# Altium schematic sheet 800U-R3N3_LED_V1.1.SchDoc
size Letter
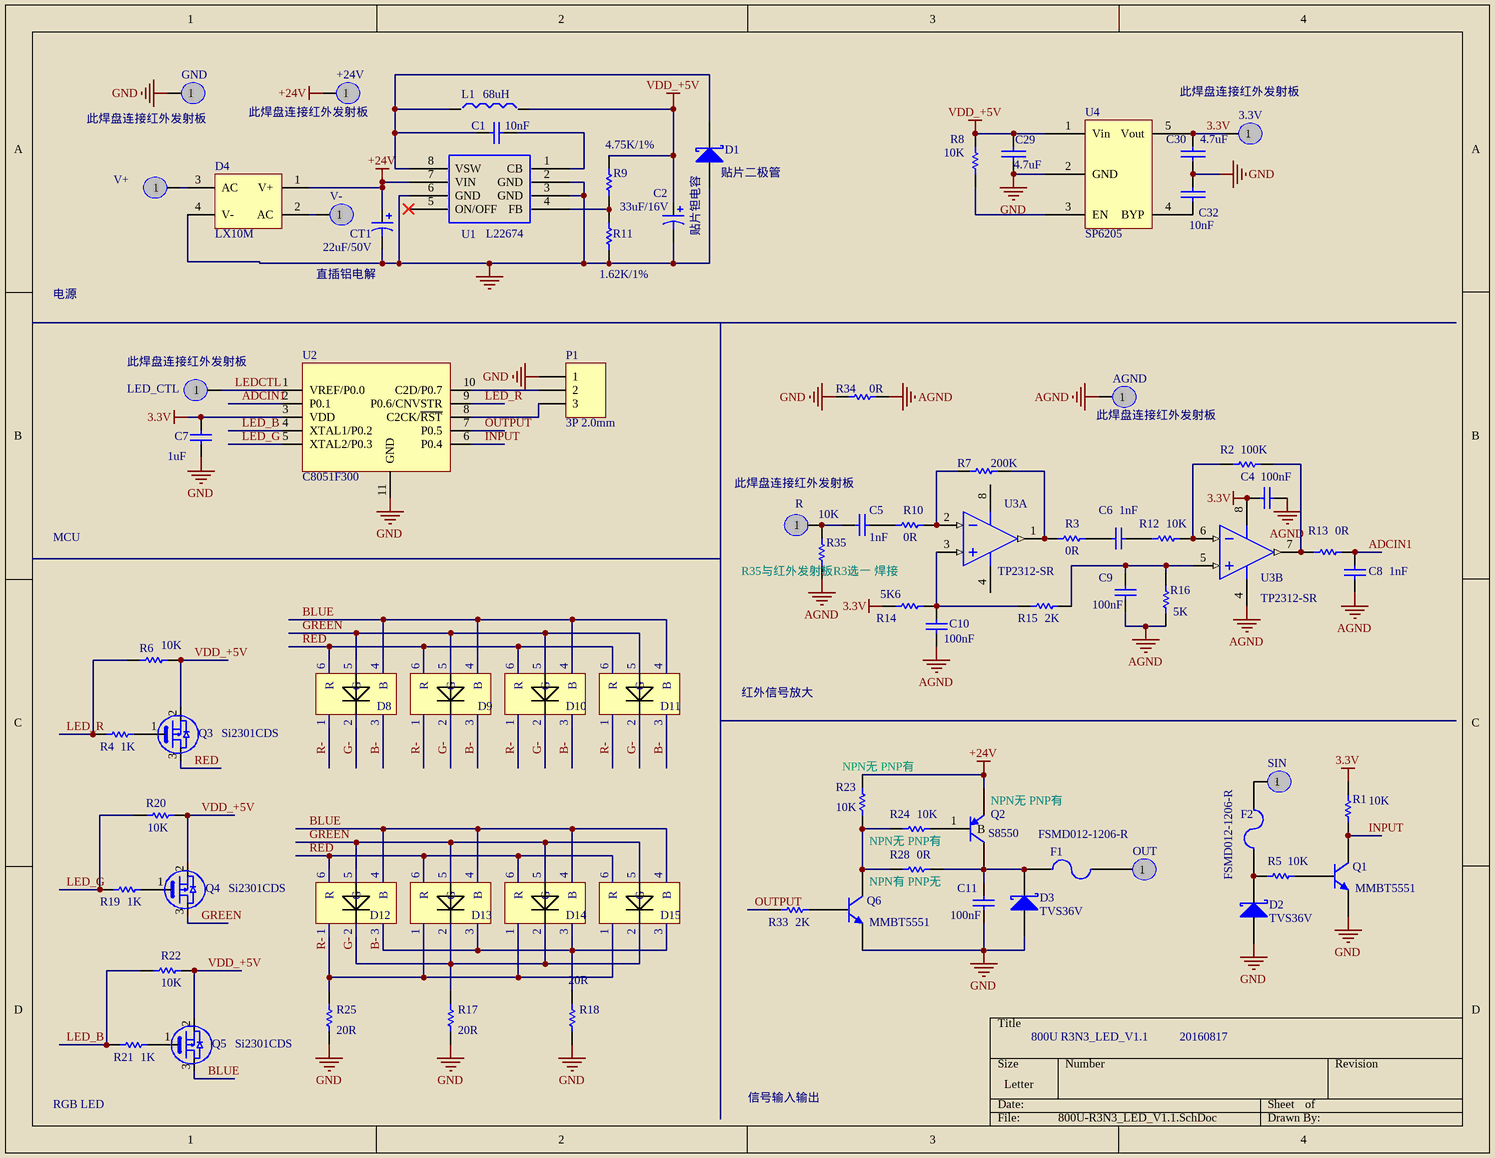
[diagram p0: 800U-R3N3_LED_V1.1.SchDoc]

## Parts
3.3V  (no value)  [HOLE_SMD]
+24V  (no value)  [HOLE_SMD]
AGND  (no value)  [HOLE_SMD]
C1  10nF  [C0603]
C2  33uF/16V  Kind: 贴片钽电容  [CT3528]
C4  100nF  [C0603]
C5  1nF  [C0603]
C6  1nF  [C0603]
C7  1uF  [C0603]
C8  1nF  [C0603]
C9  100nF  [C0603]
C10  100nF  [C0603]
C11  100nF  [C0603]
C29  4.7uF  [C0603]
C30  4.7uF  [C0603]
C32  10nF  [C0603]
CT1  22uF/50V  Kind: 直插铝电解  [RB0.1]
D1  Kind: 贴片二极管  [SMB]  (hidden comment: SS14)
D2  TVS36V  [HSMA]
D3  TVS36V  [HSMA]
D4  LX10M  [桥堆 3.8*3.5]
D8  5050RGB  [5050RGB]  (value not drawn)
D9  5050RGB  [5050RGB]  (value not drawn)
D10  5050RGB  [5050RGB]  (value not drawn)
D11  5050RGB  [5050RGB]  (value not drawn)
D12  5050RGB  [5050RGB]  (value not drawn)
D13  5050RGB  [5050RGB]  (value not drawn)
D14  5050RGB  [5050RGB]  (value not drawn)
D15  5050RGB  [5050RGB]  (value not drawn)
F1  FSMD012-1206-R  [1206]
F2  FSMD012-1206-R  [1206]
GND  (no value)  [HOLE_SMD]
L1  68uH  [L-6X6]
LED_CTL  (no value)  [HOLE_SMD]
OUT  (no value)  [HOLE_SMD]
P1  3P 2.0mm  [SIP3]
Q1  MMBT5551  [SOT-23]
Q2  S8550  [SOT-23]
Q3  Si2301CDS  [SOT-23]
Q4  Si2301CDS  [SOT-23]
Q5  Si2301CDS  [SOT-23]
Q6  MMBT5551  [SOT-23]
R  (no value)  [HOLE_SMD]
R1  10K  [R0603]
R2  100K  [R0603]
R3  0R  [R0603]
R4  1K  [R0603]
R5  10K  [R0603]
R6  10K  [R0603]
R7  200K  [R0603]
R8  10K  [R0603]
R9  4.75K/1%  [R0603]
R10  0R  [R0603]
R11  1.62K/1%  [R0603]
R12  10K  [R0603]
R13  0R  [R0603]
R14  5K6  [R0603]
R15  2K  [R0603]
R16  5K  [R0603]
R17  20R  [2010]
R18  20R  [2010]
R19  1K  [R0603]
R20  10K  [R0603]
R21  1K  [R0603]
R22  10K  [R0603]
R23  10K  [R0603]
R24  10K  [R0603]
R25  20R  [2010]
R28  0R  [R0603]
R33  2K  [R0603]
R34  0R  [R0603]
R35  10K  [R0603]
SIN  (no value)  [HOLE_SMD]
U1  L22674  [SO-1.27-9/4.0]
U2  C8051F300  [QFN-11]
U3  TP2312-SR  [SO-8]  (parts A,B of 2)
U4  SP6205  [SOT-23-5]
V+  (no value)  [HOLE_SMD]
V-  (no value)  [HOLE_SMD]

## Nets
3.3V: 3.3V.1 C4.1 C7.1 C30.1 R1.2 R14.1 U2.3(VDD) U3.8(VCC) U4.5(Vout)
+24V: +24V.1 CT1.1 D4.1(V+) Q2.2(E) R23.2 U1.7(VIN)
AGND: AGND.1 C4.2 C8.1 C9.2 C10.2 R16.1 R34.2 R35.2 U3.4(VEE)
GND: C2.2 C7.2 C11.2 C29.2 C30.2 C32.2 CT1.2 D1.1(A) D2.1(A) D3.1(A) D4.4(V-) GND.1 P1.1 Q1.2(E) Q6.2(E) R11.1 R17.1 R18.1 R25.1 R34.1 U1.2(GND) U1.3(GND) U1.6(GND) U2.11(GND) U4.2(GND)
VDD_+5V: C2.1 C29.1 L1.2 Q3.2(S) Q4.2(S) Q5.2(S) R6.1 R8.1 R9.2 R20.1 R22.1 U4.1(Vin)
ADCIN1: C8.2 R13.2 U2.2(P0.1)
B-: D8.3 D9.3 D10.3 D11.3 D12.3 D13.3 D14.3 D15.3 R18.2
BLUE: D8.4(B) D9.4(B) D10.4(B) D11.4(B) D12.4(B) D13.4(B) D14.4(B) D15.4(B) Q5.3(D)
G-: D8.2 D9.2 D10.2 D11.2 D12.2 D13.2 D14.2 D15.2 R17.2
GREEN: D8.5(G) D9.5(G) D10.5(G) D11.5(G) D12.5(G) D13.5(G) D14.5(G) D15.5(G) Q4.3(D)
INPUT: Q1.3(C) R1.1 U2.6(P0.4)
LED_B: R21.2 R22.2 U2.4(XTAL1/P0.2)
LED_G: R19.2 R20.2 U2.5(XTAL2/P0.3)
LED_R: R4.2 R6.2 U2.9(P0.6/CNVSTR)
LEDCTL: LED_CTL.1 U2.1(VREF/P0.0)
OUTPUT: R33.2 U2.7(P0.5)
R-: D8.1 D9.1 D10.1 D11.1 D12.1 D13.1 D14.1 D15.1 R25.2
RED: D8.6(R) D9.6(R) D10.6(R) D11.6(R) D12.6(R) D13.6(R) D14.6(R) D15.6(R) Q3.3(D)
NetC1_1: C1.1 U1.1(CB)
NetC1_2: C1.2 D1.2(K) L1.1 U1.8(VSW)
NetC5_1: C5.1 R.1 R35.1
NetC5_2: C5.2 R10.1
NetC6_1: C6.1 R3.2
NetC6_2: C6.2 R12.1
NetC9_1: C9.1 R15.2 R16.2 U3.5(IN+)
NetC10_1: C10.1 R14.2 R15.1 U3.3(IN+)
NetC11_1: C11.1 D3.2(K) F1.2 Q2.3(C) R28.2
NetC32_1: C32.1 U4.4(BYP)
NetD2_2: D2.2(K) F2.1 R5.1
NetD4_2: D4.2(AC) V-.1
NetD4_3: D4.3(AC) V+.1
NetF1_1: F1.1 OUT.1
NetF2_2: F2.2 SIN.1
NetP1_2: P1.2 U2.10(C2D/P0.7)
NetP1_3: P1.3 U2.8(C2CK/~{RST})
NetQ1_1: Q1.1(B) R5.2
NetQ2_1: Q2.1(B) R24.2
NetQ3_1: Q3.1(G) R4.1
NetQ4_1: Q4.1(G) R19.1
NetQ5_1: Q5.1(G) R21.1
NetQ6_1: Q6.1(B) R33.1
NetQ6_3: Q6.3(C) R23.1 R24.1 R28.1
NetR2_1: R2.1 R12.2 U3.6(IN-)
NetR2_2: R2.2 R13.1 U3.7(OUT)
NetR3_1: R3.1 R7.2 U3.1(OUT)
NetR7_1: R7.1 R10.2 U3.2(IN-)
NetR8_2: R8.2 U4.3(EN)
NetR9_1: R9.1 R11.2 U1.4(FB)

Not connected (* = marked no-connect by the designer): U1 5(ON/OFF)*

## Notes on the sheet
- 电源
- MCU
- 红外信号放大
- 800U R3N3_LED_V1.1
- 20160817
- RGB LED
- 信号输入输出

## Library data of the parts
3.3V +24V AGND GND LED_CTL OUT R SIN V+ V- = 焊盘
C1 C4-C6 C8-C10 = Cap: Capacitor; Kind: 贴片电容
C2 CT1 = Cap Pol1: Polarized Capacitor (Radial)
C7 C11 = Cap: 贴片电容
C29 C30 C32 = CAP: Capacitor; Kind: 贴片电容
D1 = SMBJ6.0CA
D2 D3 = D Schottky: 贴片TVS; Kind: 贴片二极管
D4 = Bridge2: 贴片桥堆
D8-D15 = 5050RGB: RBG发光管; Kind: 贴片LED
F1 = Fuse 2: Fuse; Kind: 贴片保险丝
F2 = Fuse 2: Fuse; kind: 贴片保险丝
L1 = 电感: Kind: 贴片电感
P1 = MHDR1X3: 插座; Kind: 下载接口
Q1 = NPN: 贴片NPN三极管; Kind: 贴片三极管
Q2 = S8550: 贴片PNP三极管; Kind: 贴片三极管
Q3-Q5 = P-MOSFET: 贴片MOS管; Kind: MOS管
Q6 = NPN: NPN三极管; Kind: 贴片三极管
R1 R4-R6 R17-R25 R28 R33 = Res Semi: 贴片电阻
R2 R3 R7 R9-R16 R34 R35 = Res Semi: Semiconductor Resistor; Kind: 贴片电阻
R8 = Res1: Resistor; Kind: 贴片电阻
U1 = 2674: Kind: 贴片芯片
U2 = PIC16C505: 贴片芯片
U3 = LM833D: Dual Low Noise, Audio Amplifier; Kind: 贴片芯片
U4 = SP6203/SP6205: Kind: 贴片芯片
